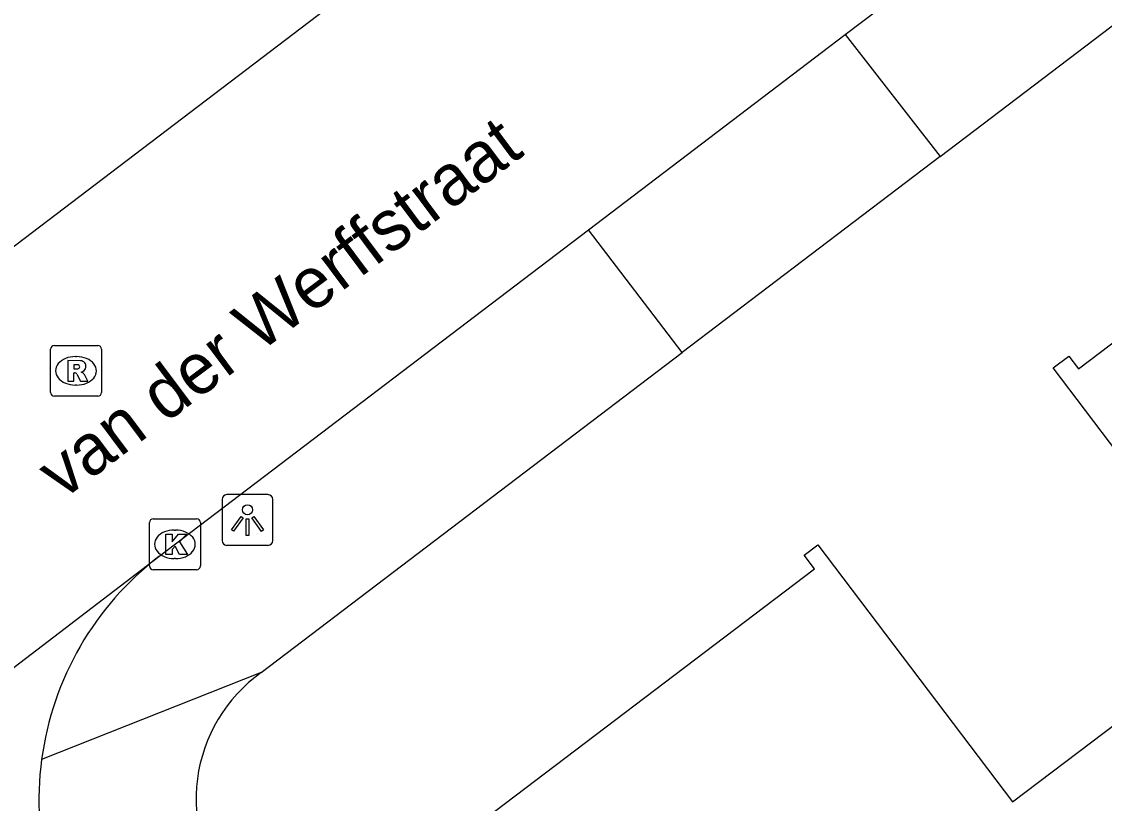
# Model space of a CAD drawing. Extents: x 160037 to 160839, y 385326 to 386441.
# Drawn here: x 160336.42 to 160357.7, y 385934.78 to 385950.14 of the extents above; entities that cross this region are included whole.
import ezdxf

# ---------------------------------------------------------------- set-up
doc = ezdxf.new("R2010")
doc.units = 0
for name, color, linetype in [('IMGEO_Kolk', 7, 'Continuous'), ('IMGEO_Lichtpunt', 7, 'Continuous'), ('IMGEO_Openbare_ruimte_label', 7, 'Continuous'), ('IMGEO_Pand', 7, 'Continuous'), ('IMGEO_Rijbaan_lokaal_open', 7, 'Continuous'), ('IMGEO_Rioolput', 7, 'Continuous'), ('IMGEO_Voetpad_open', 7, 'Continuous')]:
    doc.layers.add(name, color=color, linetype=linetype)

msp = doc.modelspace()

# ---------------------------------------------------------------- linework, layer by layer
at = {"layer": 'IMGEO_Kolk'}
for p, q in [((160338.932, 385939.441), (160338.932, 385940.293)), ((160339.007, 385940.367), (160339.859, 385940.367)), ((160339.933, 385940.293), (160339.933, 385939.441)), ((160339.42, 385940.147), (160339.445, 385940.147)), ((160339.443, 385939.587), (160339.418, 385939.587)), ((160339.859, 385939.367), (160339.007, 385939.367))]:
    msp.add_line(p, q, dxfattribs=at)
for points in [[(160338.932, 385939.441), (160338.932, 385940.293)], [(160339.007, 385940.367), (160339.859, 385940.367)], [(160339.933, 385940.293), (160339.933, 385939.441)], [(160339.253, 385940.067), (160339.376, 385940.067), (160339.376, 385939.916), (160339.506, 385940.067), (160339.67, 385940.067), (160339.524, 385939.916), (160339.677, 385939.667), (160339.525, 385939.667), (160339.44, 385939.831), (160339.376, 385939.764), (160339.376, 385939.667), (160339.253, 385939.667), (160339.253, 385940.067)], [(160339.859, 385939.367), (160339.007, 385939.367)]]:
    msp.add_lwpolyline(points, dxfattribs=at)
for centre, start, end in [((160339.009, 385940.291), 91.552, 178.448), ((160339.009, 385940.291), 91.552, 178.448), ((160339.857, 385940.291), 1.552, 88.448), ((160339.857, 385940.291), 1.552, 88.448), ((160339.009, 385939.443), 181.552, 268.448), ((160339.009, 385939.443), 181.552, 268.448), ((160339.857, 385939.443), 271.552, 358.448), ((160339.857, 385939.443), 271.552, 358.448)]:
    msp.add_arc(centre, 0.0765, start, end, dxfattribs=at)
for centre, major_axis, ratio, start_param, end_param in [((160339.419, 385939.867), (-0.387, 0.002), 0.722429, 4.712389, 7.853982), ((160339.444, 385939.867), (-0.39, 0.002), 0.717154, 1.570796, 4.712389)]:
    msp.add_ellipse(centre, major_axis=major_axis, ratio=ratio, start_param=start_param, end_param=end_param, dxfattribs=at)
at = {"layer": 'IMGEO_Lichtpunt'}
for p, q in [((160341.262, 385940.843), (160340.454, 385940.843)), ((160341.262, 385940.843), (160340.454, 385940.843)), ((160340.36, 385940.748), (160340.36, 385939.941)), ((160340.36, 385940.748), (160340.36, 385939.941)), ((160341.356, 385939.941), (160341.356, 385940.748)), ((160341.356, 385939.941), (160341.356, 385940.748)), ((160340.454, 385939.847), (160341.262, 385939.847)), ((160340.454, 385939.847), (160341.262, 385939.847))]:
    msp.add_line(p, q, dxfattribs=at)
for points in [[(160340.734, 385940.412), (160340.773, 385940.384), (160340.585, 385940.122), (160340.547, 385940.149), (160340.734, 385940.412)], [(160340.946, 385940.384), (160340.984, 385940.411), (160341.171, 385940.149), (160341.132, 385940.121), (160340.946, 385940.384)], [(160340.836, 385940.364), (160340.883, 385940.364), (160340.883, 385940.042), (160340.836, 385940.042), (160340.836, 385940.364)]]:
    msp.add_lwpolyline(points, dxfattribs=at)
msp.add_circle((160340.859, 385940.546), 0.0994, dxfattribs=at)
for centre, start, end in [((160340.454, 385940.748), 90, 180), ((160340.454, 385940.748), 90, 180), ((160341.262, 385940.748), 0, 90), ((160341.262, 385940.748), 0, 90), ((160340.454, 385939.941), 180, 270), ((160340.454, 385939.941), 180, 270), ((160341.262, 385939.941), 270, 0), ((160341.262, 385939.941), 270, 360)]:
    msp.add_arc(centre, 0.0946, start, end, dxfattribs=at)
at = {"layer": 'IMGEO_Pand'}
for points in [[(160358.206, 385936.557), (160360.511, 385938.305), (160356.698, 385943.335), (160357.002, 385943.565), (160357.193, 385943.313), (160362.442, 385947.292)], [(160341.418, 385931.706), (160341.644, 385931.877), (160341.812, 385931.655), (160352.005, 385939.382), (160351.798, 385939.655), (160352.068, 385939.859), (160355.898, 385934.808), (160358.206, 385936.557)]]:
    msp.add_lwpolyline(points, dxfattribs=at)
at = {"layer": 'IMGEO_Rijbaan_lokaal_open'}
for points in [[(160359.957, 385963.714), (160354.853, 385959.852), (160335.37, 385945.037), (160332.879, 385943.015), (160325.513, 385936.326), (160323.295, 385934.312), (160321.054, 385932.279)], [(160352.608, 385949.882), (160353.274, 385950.388)], [(160347.562, 385946.047), (160352.608, 385949.882)], [(160339.117, 385939.628), (160347.562, 385946.047)], [(160324.349, 385928.333), (160324.413, 385928.386), (160339.117, 385939.628)]]:
    msp.add_lwpolyline(points, dxfattribs=at)
for centre, radius, start, end in [((160342.807, 385934.835), 6.048, 127.591, 172.3546), ((160342.804, 385934.84), 6.045, 172.3937, 217.1871)]:
    msp.add_arc(centre, radius, start, end, dxfattribs=at)
at = {"layer": 'IMGEO_Rioolput'}
for p, q in [((160336.988, 385942.849), (160336.988, 385943.701)), ((160337.063, 385943.775), (160337.915, 385943.775)), ((160337.989, 385943.701), (160337.989, 385942.849)), ((160337.476, 385943.555), (160337.501, 385943.555)), ((160337.499, 385942.995), (160337.474, 385942.995)), ((160337.915, 385942.775), (160337.063, 385942.775))]:
    msp.add_line(p, q, dxfattribs=at)
for points in [[(160336.988, 385942.849), (160336.988, 385943.701)], [(160337.063, 385943.775), (160337.915, 385943.775)], [(160337.989, 385943.701), (160337.989, 385942.849)], [(160337.577, 385943.473), (160337.325, 385943.475), (160337.325, 385943.075)], [(160337.503, 385943.394), (160337.449, 385943.394), (160337.449, 385943.313)], [(160337.325, 385943.075), (160337.449, 385943.075), (160337.449, 385943.237), (160337.46, 385943.237)], [(160337.449, 385943.313), (160337.501, 385943.313)], [(160337.507, 385943.208), (160337.578, 385943.075), (160337.718, 385943.075), (160337.653, 385943.201)], [(160337.915, 385942.775), (160337.063, 385942.775)]]:
    msp.add_lwpolyline(points, dxfattribs=at)
for centre, radius, start, end in [((160337.065, 385943.699), 0.0765, 91.552, 178.448), ((160337.065, 385943.699), 0.0765, 91.552, 178.448), ((160337.913, 385943.699), 0.0765, 1.552, 88.448), ((160337.913, 385943.699), 0.0765, 1.552, 88.448), ((160337.509, 385943.298), 0.0964, 77.0061, 93.1865), ((160337.523, 385943.355), 0.0378, 276.6634, 79.6772), ((160337.576, 385943.363), 0.109, 350.3612, 89.416), ((160337.459, 385943.184), 0.0533, 26.0293, 88.6989), ((160337.485, 385943.502), 0.19, 274.7715, 282.9687), ((160337.574, 385943.363), 0.112, 277.5842, 350.9817), ((160337.558, 385943.148), 0.108, 29.5134, 73.7905), ((160337.065, 385942.851), 0.0765, 181.552, 268.448), ((160337.065, 385942.851), 0.0765, 181.552, 268.448), ((160337.913, 385942.851), 0.0765, 271.552, 358.448), ((160337.913, 385942.851), 0.0765, 271.552, 358.448)]:
    msp.add_arc(centre, radius, start, end, dxfattribs=at)
for centre, major_axis, ratio, start_param, end_param in [((160337.475, 385943.275), (-0.387, 0.002), 0.722429, 4.712389, 7.853982), ((160337.5, 385943.275), (-0.39, 0.002), 0.717154, 1.570796, 4.712389)]:
    msp.add_ellipse(centre, major_axis=major_axis, ratio=ratio, start_param=start_param, end_param=end_param, dxfattribs=at)
at = {"layer": 'IMGEO_Voetpad_open'}
for points in [[(160354.473, 385947.484), (160375.169, 385963.208)], [(160352.608, 385949.882), (160354.473, 385947.484)], [(160354.473, 385947.484), (160349.403, 385943.633)], [(160349.403, 385943.633), (160347.562, 385946.047)], [(160341.128, 385937.346), (160349.403, 385943.633)], [(160341.128, 385937.346), (160336.812, 385935.64)]]:
    msp.add_lwpolyline(points, dxfattribs=at)
msp.add_arc((160342.894, 385934.866), 3.044, 125.4568, 219.7678, dxfattribs=at)

# ---------------------------------------------------------------- texts
at = {"layer": 'IMGEO_Openbare_ruimte_label'}
msp.add_text('van der Werffstraat', height=1, rotation=36.7897, dxfattribs=at).set_placement((160337.218, 385940.723))

doc.saveas('drawing.dxf')
